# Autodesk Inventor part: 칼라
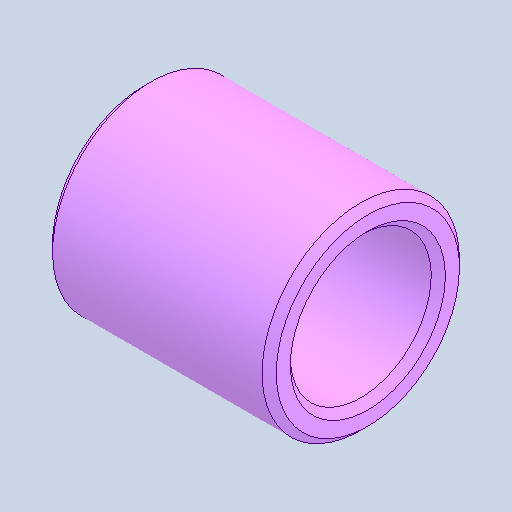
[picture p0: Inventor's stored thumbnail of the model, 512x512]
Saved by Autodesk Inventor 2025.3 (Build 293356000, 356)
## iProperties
Created: 2026-01
Part Number: 칼라
Material: 강철, 연강
Document SubType Name: Modeling
Designer: PC-13
Density: 7.85 g/cm^3
Appearance: 기본값
Author: jhkim
Sending System: Autodesk Inventor 2026
Preprocessor: ST-DEVELOPER v20.1
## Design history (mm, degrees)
feature "솔리드1"
node "솔리드2"
